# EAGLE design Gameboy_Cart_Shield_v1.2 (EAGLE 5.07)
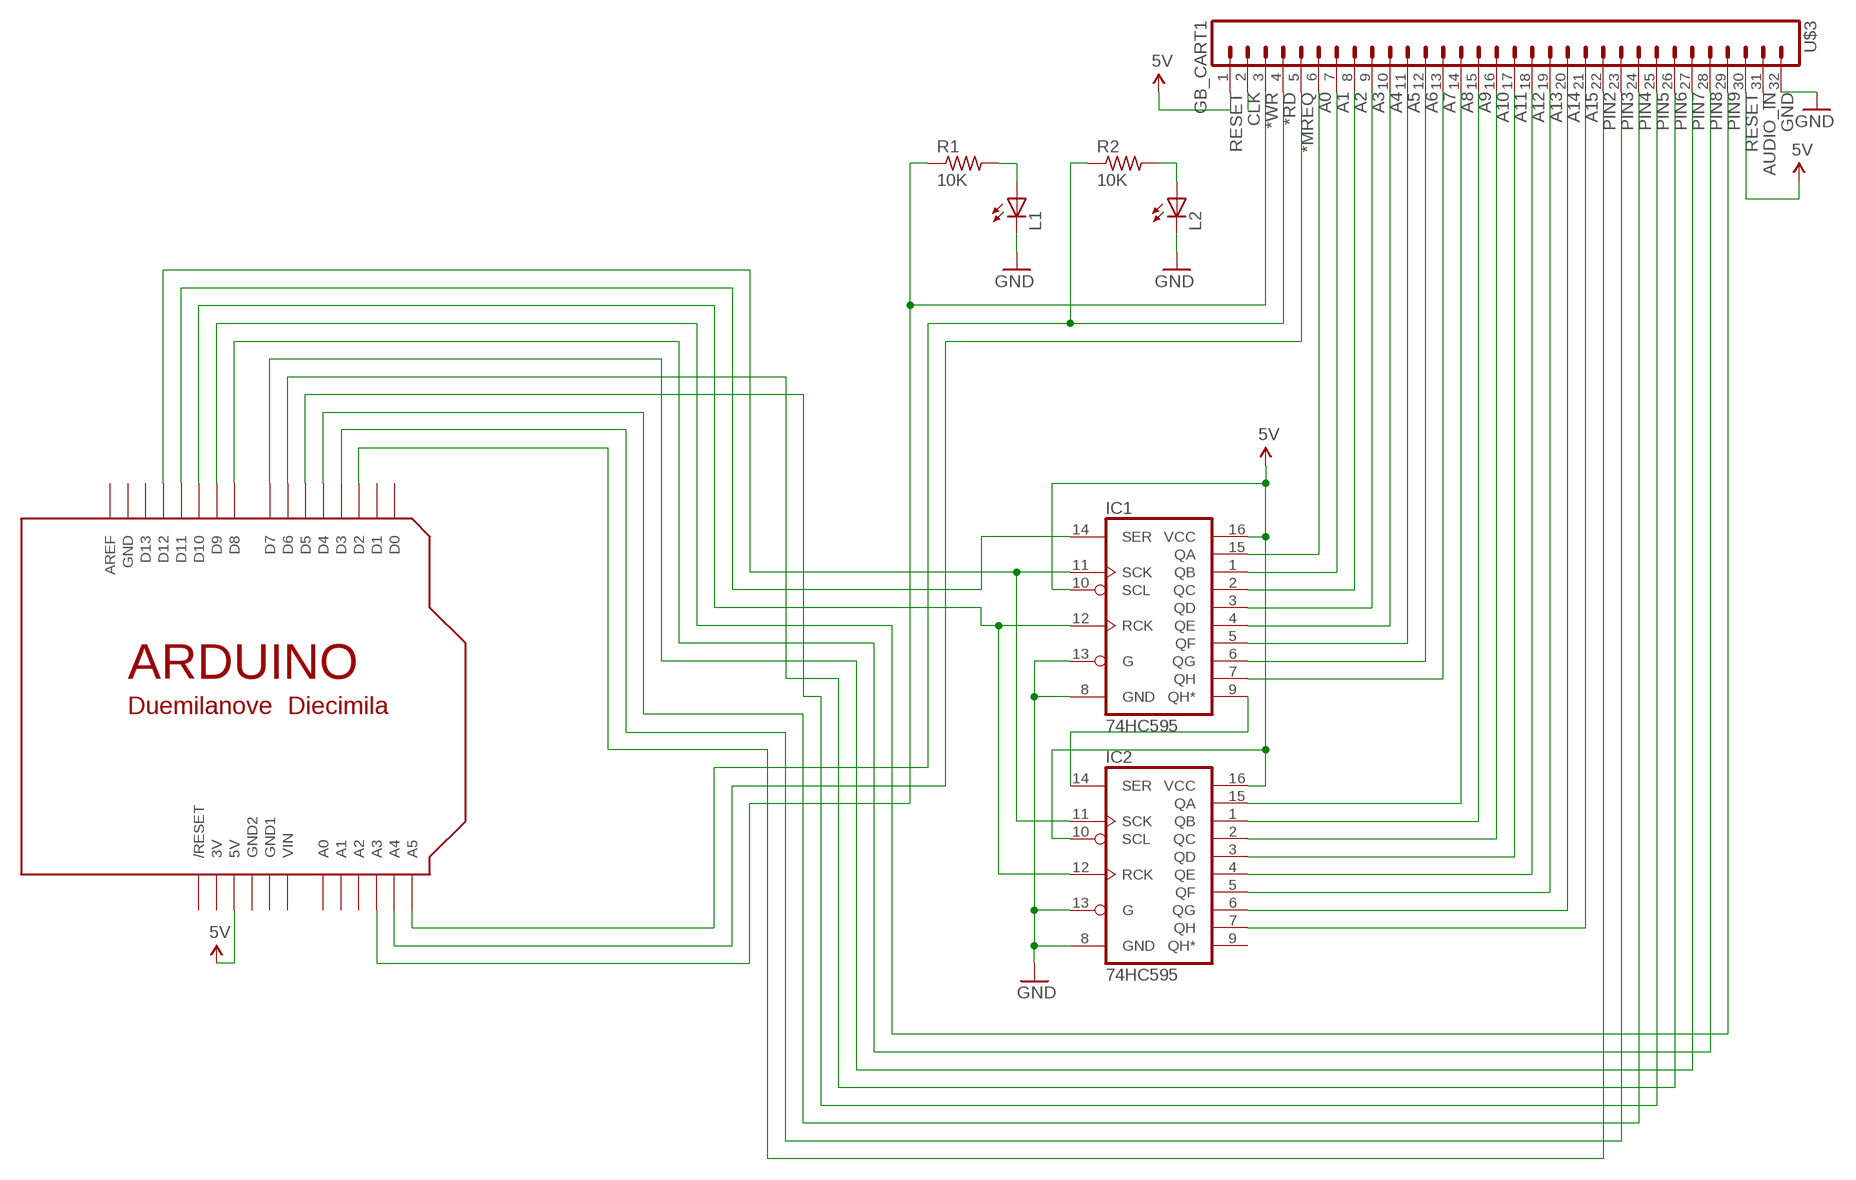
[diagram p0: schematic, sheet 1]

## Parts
IC1  74HC595  74LS595D  [SO16]
IC2  74HC595  74LS595D  [SO16]
L1  LEDCHIP-LED0805  [CHIP-LED0805]
L2  LEDCHIP-LED0805  [CHIP-LED0805]
R1  10K  R-US_R0805_2  [R0805_2]
R2  10K  R-US_R0805_2  [R0805_2]
U$1  ARDUINONODIMA  [ARDUINO-NODIMA]
U$3  GB_CART1  [GB_CART_1]

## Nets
*MREQ: U$1.A4 U$3.5
*RD: R2.1 U$1.A5 U$3.4
*WR: R1.1 U$1.A3 U$3.3
A0: IC1.15(QA) U$3.6
A1: IC1.1(QB) U$3.7
A2: IC1.2(QC) U$3.8
A3: IC1.3(QD) U$3.9
A4: IC1.4(QE) U$3.10
A5: IC1.5(QF) U$3.11
A6: IC1.6(QG) U$3.12
A7: IC1.7(QH) U$3.13
A8: IC2.15(QA) U$3.14
A9: IC2.1(QB) U$3.15
A10: IC2.2(QC) U$3.16
A11: IC2.3(QD) U$3.17
A12: IC2.4(QE) U$3.18
A13: IC2.5(QF) U$3.19
A14: IC2.6(QG) U$3.20
A15: IC2.7(QH) U$3.21
AUDIO_IN: U$3.31
CLK: U$3.2
GND: IC1.8(GND) IC1.13(G) IC2.8(GND) IC2.13(G) L1.C L2.C U$3.32
N$1: L2.A R2.2
N$6: L1.A R1.2
N$10: IC1.9(QH*) IC2.14(SER)
PIN2: U$1.D2 U$3.22
PIN3: U$1.D3 U$3.23
PIN4: U$1.D4 U$3.24
PIN5: U$1.D5 U$3.25
PIN6: U$1.D6 U$3.26
PIN7: U$1.D7 U$3.27
PIN8: U$1.D8 U$3.28
PIN9: U$1.D9 U$3.29
PIN10: IC1.12(RCK) IC2.12(RCK) U$1.D10
PIN11: IC1.14(SER) U$1.D11
PIN12: IC1.11(SCK) IC2.11(SCK) U$1.D12
RESET: IC1.10(SCL) IC1.16(VCC) IC2.10(SCL) IC2.16(VCC) U$1.5V U$3.1 U$3.30 ; supply symbol labelled 5V
Unconnected: IC2.9(QH*) U$1.A0 U$1.A1 U$1.A2 U$1.AREF U$1.D0 U$1.D1 U$1.D13 U$1.RESET(/RESET)

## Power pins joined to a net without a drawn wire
3V: U$1.3V
GND: U$1.GND
GND1: U$1.GND1
GND2: U$1.GND2
VIN: U$1.VIN

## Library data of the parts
IC1 IC2 = SparkFun:74*595: 8-bit SHIFT REGISTER, output latch
L1 L2 = adafruit:LED: LED
R1 R2 = adafruit:R-US_: RESISTOR, American symbol
U$1 = adafruit:ARDUINO: Arduino Diecimila/Duemilanove Make a shield with ease, this package has all the named pins as well as the two mounting drill holes and an outline of the USB and DC power connector. The outline is on the DIMENSION layer, so if your board house uses it they will cut the outline to match.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
U$3 = alex:GB_CART

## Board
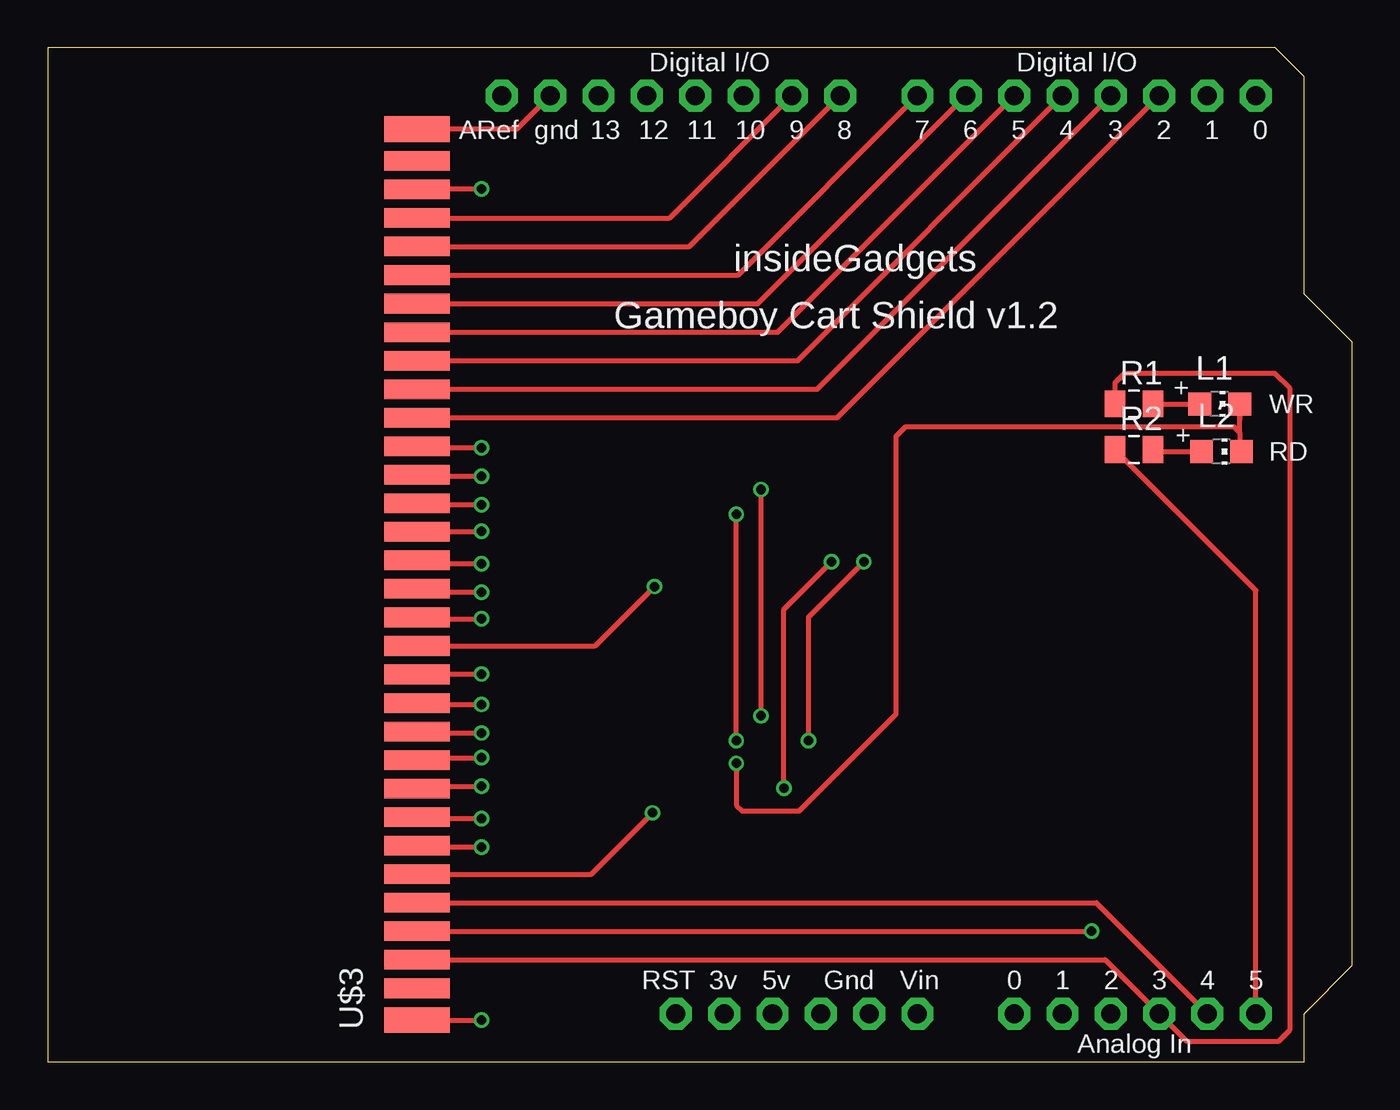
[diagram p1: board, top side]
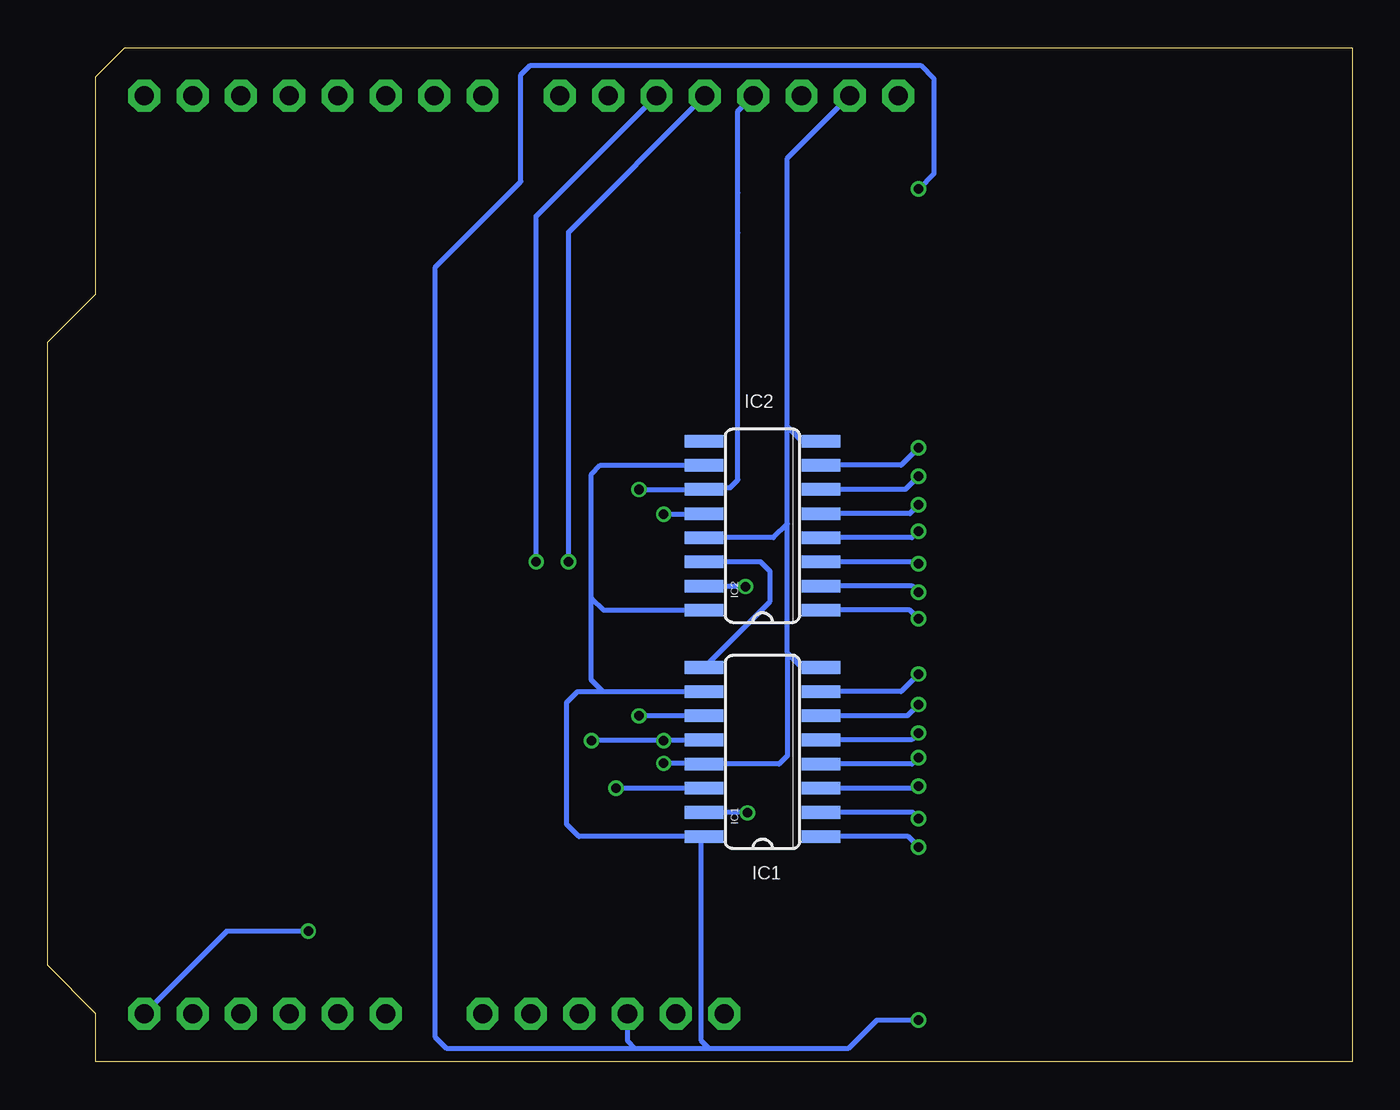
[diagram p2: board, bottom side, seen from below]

Size 68.58 x 53.34 mm. Coordinates in mm from the lower left corner, seen from the top.
Copper layers (1*16): Top 0.035mm / dielectric 1.5mm / Bottom 0.035mm
Design rules "ITEADstudio_DRC": minimum track width 6mil, minimum drill 12mil, track to track 6mil, track to pad 6mil, pad to pad 6mil, via to via 6mil, smd to smd 0mil, copper to edge 10mil, drill to drill 10mil, minimum pad ring 10mil, minimum via ring 6mil, stop-mask expansion 2mil, vias tented up to drill 100mil, thermal gap 10mil

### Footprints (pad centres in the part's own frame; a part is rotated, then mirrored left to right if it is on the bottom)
SO16 = smd 0.66 x 2.032: 1 -4.445,-3.073; 2 -3.175,-3.073; 3 -1.905,-3.073; 4 -0.635,-3.073; 5 0.635,-3.073; 6 1.905,-3.073; 7 3.175,-3.073; 8 4.445,-3.073; 9 4.445,3.073; 10 3.175,3.073; 11 1.905,3.073; 12 0.635,3.073; 13 -0.635,3.073; 14 -1.905,3.073; 15 -3.175,3.073; 16 -4.445,3.073
CHIP-LED0805 = smd 1.2 x 1.2: A 0,-1.05; C 0,1.05
R0805_2 = smd 1.1 x 1.4: 1 -1,0; 2 1,0
ARDUINO-NODIMA = drill 1 pad 1.676 octagon: 3V 35.56,2.54; 5V 38.1,2.54; A0 50.8,2.54; A1 53.34,2.54; A2 55.88,2.54; A3 58.42,2.54; A4 60.96,2.54; A5 63.5,2.54; AREF 23.876,50.8; D0 63.5,50.8; D1 60.96,50.8; D2 58.42,50.8; D3 55.88,50.8; D4 53.34,50.8; D5 50.8,50.8; D6 48.26,50.8; D7 45.72,50.8; D8 41.656,50.8; D9 39.116,50.8; D10 36.576,50.8; D11 34.036,50.8; D12 31.496,50.8; D13 28.956,50.8; GND 26.416,50.8; GND1 43.18,2.54; GND2 40.64,2.54; RESET 33.02,2.54; VIN 45.72,2.54
GB_CART_1 = smd 1.36 x 3.46: 1 -22.895,-0.12; 32 23.94,-0.12 | smd 1.03 x 3.46: 2 -21.225,-0.12; 3 -19.725,-0.12; 4 -18.225,-0.12; 5 -16.725,-0.12; 6 -15.225,-0.12; 7 -13.725,-0.12; 8 -12.225,-0.12; 9 -10.725,-0.12; 10 -9.225,-0.12; 11 -7.725,-0.12; 12 -6.225,-0.12; 13 -4.725,-0.12; 14 -3.225,-0.12; 15 -1.725,-0.12; 16 -0.225,-0.12; 17 1.275,-0.12; 18 2.775,-0.12; 19 4.275,-0.12; 20 5.775,-0.12; 21 7.275,-0.12; 22 8.775,-0.12; 23 10.275,-0.12; 24 11.775,-0.12; 25 13.275,-0.12; 26 14.775,-0.12; 27 16.275,-0.12; 28 17.775,-0.12; 29 19.275,-0.12; 30 20.775,-0.12; 31 22.275,-0.12

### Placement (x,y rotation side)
IC1  31,16.3 90 bottom
IC2  31,28.2 90 bottom
L1  61.6,34.6 270 top
L2  61.7,32.1 270 top
R1  57.1,34.6 0 top
R2  57.1,32.2 0 top
U$1  0,0 0 top
U$3  19.3,25.1 90 top

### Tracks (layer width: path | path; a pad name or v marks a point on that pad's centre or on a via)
*MREQ
  Top 0.254: U$3.5 55.12,8.38 U$1.A4
*RD  (via drill 0.5)
  Top 0.254: 19.42,6.9 U$3.4 v54.88,6.88 | U$1.A5 63.5,24.8 R2.1
  Bottom 0.254: v54.88,6.88 59.16,6.88 U$1.A5
*WR
  Top 0.254: U$3.3 55.58,5.38 U$1.A3 59.86,1.1 64.7,1.1 65.3,1.7 65.3,35.4 64.5,36.2 56.6,36.2 56.1,35.7 R1.1
A0  (via drill 0.5)
  Top 0.254: v31.8,13.1 28.58,9.88 U$3.6
  Bottom 0.254: v31.8,13.1 31.83,13.13 IC1.15
A1  (via drill 0.5)
  Top 0.254: U$3.7 19.49,11.3 v22.8,11.3
  Bottom 0.254: IC1.1 23.36,11.86 v22.8,11.3
A2  (via drill 0.5)
  Top 0.254: U$3.8 19.49,12.8 v22.8,12.8
  Bottom 0.254: v22.8,12.8 23.12,13.13 IC1.2
A3  (via drill 0.5)
  Top 0.254: U$3.9 19.55,14.5 v22.8,14.5
  Bottom 0.254: IC1.3 22.91,14.4 v22.8,14.5
A4  (via drill 0.5)
  Top 0.254: v22.8,16 19.55,16 U$3.10
  Bottom 0.254: IC1.4 23.13,15.67 v22.8,16
A5  (via drill 0.5)
  Top 0.254: v22.8,17.3 19.49,17.3 U$3.11
  Bottom 0.254: IC1.5 23.16,16.94 v22.8,17.3
A6  (via drill 0.5)
  Top 0.254: v22.8,18.8 19.49,18.8 U$3.12
  Bottom 0.254: IC1.6 23.39,18.21 v22.8,18.8
A7  (via drill 0.5)
  Top 0.254: v22.8,20.4 19.44,20.4 U$3.13
  Bottom 0.254: IC1.7 23.72,19.48 v22.8,20.4
A8  (via drill 0.5)
  Top 0.254: v31.9,25 28.77,21.88 U$3.14
  Bottom 0.254: v31.9,25 34.05,25 IC2.15
A9  (via drill 0.5)
  Top 0.254: v22.8,23.3 19.49,23.3 U$3.15
  Bottom 0.254: IC2.1 23.25,23.76 v22.8,23.3
A10  (via drill 0.5)
  Top 0.254: v22.8,24.7 19.59,24.7 U$3.16
  Bottom 0.254: IC2.2 23.12,25.03 v22.8,24.7
A11  (via drill 0.5)
  Top 0.254: v22.8,26.2 19.59,26.2 U$3.17
  Bottom 0.254: IC2.3 22.89,26.3 v22.8,26.2
A12  (via drill 0.5)
  Top 0.254: v22.8,27.9 19.44,27.9 U$3.18
  Bottom 0.254: IC2.4 23.13,27.57 v22.8,27.9
A13  (via drill 0.5)
  Top 0.254: v22.8,29.3 19.49,29.3 U$3.19
  Bottom 0.254: IC2.5 23.27,28.84 v22.8,29.3
A14  (via drill 0.5)
  Top 0.254: v22.8,30.8 19.49,30.8 U$3.20
  Bottom 0.254: IC2.6 23.49,30.11 v22.8,30.8
A15  (via drill 0.5)
  Top 0.254: v22.8,32.3 19.49,32.3 U$3.21
  Bottom 0.254: IC2.7 23.72,31.38 v22.8,32.3
GND  (via drill 0.5)
  Top 0.254: U$3.32 24.66,49.04 U$1.GND | 62.65,33.1 62.65,32.2 L2.C | 62.65,33.1 L1.C 62.65,33.75 | 62.65,33.1 62.35,33.4 45.1,33.4 44.6,32.9 44.6,18.3 39.5,13.2 36.5,13.2 36.2,13.5 v36.2,15.7
  Bottom 0.254: 27.98,32.7 IC2.8 28.94,32.65 29.7,33.4 | 29.7,28.3 29.7,33.4 | IC2.13 30.44,27.57 29.7,28.3 | 29.7,21.5 29.7,16.1 30.13,15.67 IC1.13 34.07,15.7 v36.2,15.7 | 29.7,21.5 29.7,28.3 | IC1.8 28.94,20.75 29.7,21.5 | U$1.GND 29.7,47.52 29.7,33.4
N$1
  Top 0.254: L2.A 58,32.1 R2.2
N$6
  Top 0.254: R1.2 L1.A
N$10
  Bottom 0.254: IC2.14 31.11,26.3 31.1,26.3 30.6,25.8 30.6,24.22 IC1.9
PIN2
  Top 0.254: U$1.D2 41.49,33.88 U$3.22
PIN3
  Top 0.254: U$1.D3 40.45,35.38 U$3.23
PIN4
  Top 0.254: U$1.D4 39.41,36.88 U$3.24
PIN5
  Top 0.254: U$1.D5 38.38,38.38 U$3.25
PIN6
  Top 0.254: U$1.D6 37.33,39.88 U$3.26
PIN7
  Top 0.254: U$1.D7 36.3,41.38 U$3.27
PIN8
  Top 0.254: U$1.D8 33.73,42.88 U$3.28
PIN9
  Top 0.254: U$1.D9 32.69,44.38 U$3.29
PIN10  (via drill 0.5)
  Top 0.254: v36.2,16.9 v36.2,28.8 | v40,16.9 40,23.4 v42.9,26.3
  Bottom 0.254: IC2.12 34.11,28.8 v36.2,28.8 | IC1.12 34.11,16.9 v36.2,16.9 v40,16.9 | U$1.D10 42.9,44.48 v42.9,26.3
PIN11  (via drill 0.5)
  Top 0.254: v38.7,14.4 38.7,23.8 v41.2,26.3
  Bottom 0.254: IC1.14 38.99,14.4 v38.7,14.4 | U$1.D11 41.2,43.64 v41.2,26.3
PIN12  (via drill 0.5)
  Top 0.254: v37.5,18.2 v37.5,30.1
  Bottom 0.254: v37.5,30.1 34.27,30.1 34.17,30.2 IC2.11 33.98,30.2 32.7,30.2 32.3,30.6 32.3,43.6 32.3,45.7 32.3,50 U$1.D12 | IC1.11 v37.5,18.2
RESET  (via drill 0.5)
  Top 0.254: v22.8,45.9 19.44,45.9 U$3.30 | U$3.1 v22.8,2.2
  Bottom 0.254: 33.8,0.7 26.5,0.7 25,2.2 v22.8,2.2 | 33.8,0.7 37.68,0.7 | 37.68,0.7 47.6,0.7 48.2,1.3 48.2,41.8 43.7,46.3 43.7,51.9 43.2,52.4 22.7,52.4 22,51.7 22,46.7 v22.8,45.9 | 34.12,23.8 IC2.16 39.36,23.76 40,24.4 | 33.8,0.7 34.22,1.12 34.22,12 IC1.16 40.66,11.86 41.3,12.5 41.3,18.9 40.72,19.48 39.4,19.48 | IC2.10 39.52,31.38 40,30.9 40,24.4 | 39.4,19.48 IC1.10 | 40,24.4 40,20.08 39.4,19.48 | U$1.5V 38.1,1.12 37.68,0.7

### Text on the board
_tsilk: insideGadgets | Gameboy Cart Shield v1.2 | WR | RD
_bsilk: IC2 | IC1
